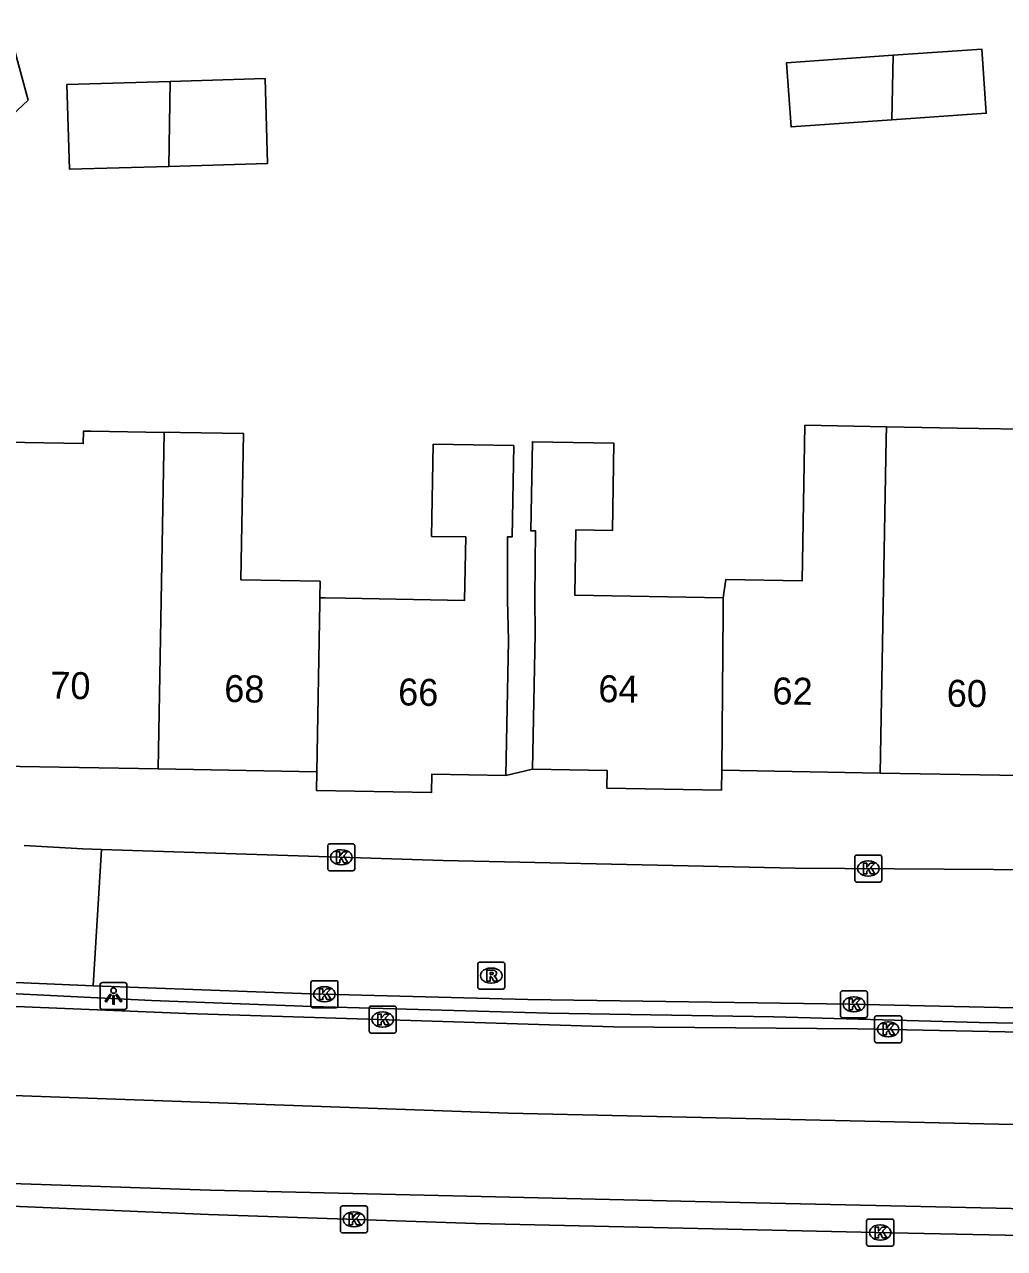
# Model space of a CAD drawing. Extents: x 161845 to 162341, y 381620 to 382158.
# Drawn here: x 162083.32 to 162119.6, y 381620.6 to 381665.94 of the extents above; entities that cross this region are included whole.
import ezdxf

# ---------------------------------------------------------------- set-up
doc = ezdxf.new("R2010")
doc.units = 0
for name, color, linetype in [('IMGEO_Hek', 7, 'Continuous'), ('IMGEO_Kolk', 7, 'Continuous'), ('IMGEO_Lichtpunt', 7, 'Continuous'), ('IMGEO_Pand', 7, 'Continuous'), ('IMGEO_Pand_nummerreeks', 7, 'Continuous'), ('IMGEO_Rijbaan_lokaal_open', 7, 'Continuous'), ('IMGEO_Rijbaan_regionaal_gesloten', 7, 'Continuous'), ('IMGEO_Rioolput', 7, 'Continuous'), ('IMGEO_Voetpad_open', 7, 'Continuous')]:
    doc.layers.add(name, color=color, linetype=linetype)

msp = doc.modelspace()

# ---------------------------------------------------------------- linework, layer by layer
at = {"layer": 'IMGEO_Hek'}
msp.add_lwpolyline([(162137.794, 381628.704), (162131.639, 381628.756), (162127.198, 381628.815), (162118.656, 381628.981), (162111.06, 381629.186), (162102.721, 381629.322), (162093.959, 381629.569), (162088.027, 381629.796), (162079.036, 381630.235), (162074.46, 381630.502), (162066.472, 381631.038), (162058.311, 381631.695), (162053.276, 381632.163), (162034.557, 381634.329), (162000, 381638.941), (161983.372, 381641.239)], dxfattribs=at)
at = {"layer": 'IMGEO_Kolk'}
for p, q in [((162094.547, 381634.669), (162094.547, 381635.521)), ((162094.622, 381635.595), (162095.474, 381635.595)), ((162095.035, 381635.375), (162095.06, 381635.375)), ((162095.548, 381635.521), (162095.548, 381634.669)), ((162114.132, 381635.179), (162114.984, 381635.179)), ((162095.058, 381634.815), (162095.033, 381634.815)), ((162114.057, 381634.253), (162114.057, 381635.105)), ((162114.545, 381634.959), (162114.57, 381634.959)), ((162115.058, 381635.105), (162115.058, 381634.253)), ((162095.474, 381634.595), (162094.622, 381634.595)), ((162114.568, 381634.399), (162114.543, 381634.399)), ((162114.984, 381634.179), (162114.132, 381634.179)), ((162093.926, 381629.597), (162093.926, 381630.449)), ((162094.001, 381630.523), (162094.853, 381630.523)), ((162094.414, 381630.303), (162094.439, 381630.303)), ((162094.927, 381630.449), (162094.927, 381629.597)), ((162094.437, 381629.743), (162094.412, 381629.743)), ((162113.526, 381629.224), (162113.526, 381630.076)), ((162113.601, 381630.15), (162114.453, 381630.15)), ((162114.014, 381629.93), (162114.039, 381629.93)), ((162114.527, 381630.076), (162114.527, 381629.224)), ((162094.853, 381629.523), (162094.001, 381629.523)), ((162096.082, 381628.66), (162096.082, 381629.512)), ((162096.157, 381629.586), (162097.009, 381629.586)), ((162096.57, 381629.366), (162096.595, 381629.366)), ((162097.083, 381629.512), (162097.083, 381628.66)), ((162114.037, 381629.37), (162114.012, 381629.37)), ((162096.593, 381628.806), (162096.568, 381628.806)), ((162114.453, 381629.15), (162113.601, 381629.15)), ((162114.792, 381628.297), (162114.792, 381629.149)), ((162114.867, 381629.223), (162115.719, 381629.223)), ((162115.28, 381629.003), (162115.305, 381629.003)), ((162115.793, 381629.149), (162115.793, 381628.297)), ((162097.009, 381628.586), (162096.157, 381628.586)), ((162115.303, 381628.443), (162115.278, 381628.443)), ((162115.719, 381628.223), (162114.867, 381628.223)), ((162095.018, 381621.259), (162095.018, 381622.111)), ((162095.093, 381622.185), (162095.945, 381622.185)), ((162096.019, 381622.111), (162096.019, 381621.259)), ((162095.506, 381621.965), (162095.531, 381621.965)), ((162114.496, 381620.771), (162114.496, 381621.623)), ((162114.571, 381621.697), (162115.423, 381621.697)), ((162115.497, 381621.623), (162115.497, 381620.771)), ((162095.945, 381621.185), (162095.093, 381621.185)), ((162095.529, 381621.405), (162095.504, 381621.405)), ((162114.984, 381621.477), (162115.009, 381621.477)), ((162115.423, 381620.697), (162114.571, 381620.697)), ((162115.007, 381620.917), (162114.982, 381620.917))]:
    msp.add_line(p, q, dxfattribs=at)
for points in [[(162094.547, 381634.669), (162094.547, 381635.521)], [(162094.622, 381635.595), (162095.474, 381635.595)], [(162094.868, 381635.295), (162094.991, 381635.295), (162094.991, 381635.144), (162095.121, 381635.295), (162095.285, 381635.295), (162095.139, 381635.144), (162095.292, 381634.895), (162095.14, 381634.895), (162095.055, 381635.059), (162094.991, 381634.992), (162094.991, 381634.895), (162094.868, 381634.895), (162094.868, 381635.295)], [(162095.548, 381635.521), (162095.548, 381634.669)], [(162114.132, 381635.179), (162114.984, 381635.179)], [(162114.057, 381634.253), (162114.057, 381635.105)], [(162114.378, 381634.879), (162114.501, 381634.879), (162114.501, 381634.728), (162114.631, 381634.879), (162114.795, 381634.879), (162114.649, 381634.728), (162114.802, 381634.479), (162114.65, 381634.479), (162114.565, 381634.643), (162114.501, 381634.576), (162114.501, 381634.479), (162114.378, 381634.479), (162114.378, 381634.879)], [(162115.058, 381635.105), (162115.058, 381634.253)], [(162095.474, 381634.595), (162094.622, 381634.595)], [(162114.984, 381634.179), (162114.132, 381634.179)], [(162093.926, 381629.597), (162093.926, 381630.449)], [(162094.001, 381630.523), (162094.853, 381630.523)], [(162094.247, 381630.223), (162094.37, 381630.223), (162094.37, 381630.072), (162094.5, 381630.223), (162094.664, 381630.223), (162094.518, 381630.072), (162094.671, 381629.823), (162094.519, 381629.823), (162094.434, 381629.987), (162094.37, 381629.92), (162094.37, 381629.823), (162094.247, 381629.823), (162094.247, 381630.223)], [(162094.927, 381630.449), (162094.927, 381629.597)], [(162113.526, 381629.224), (162113.526, 381630.076)], [(162113.601, 381630.15), (162114.453, 381630.15)], [(162113.847, 381629.85), (162113.97, 381629.85), (162113.97, 381629.699), (162114.1, 381629.85), (162114.264, 381629.85), (162114.118, 381629.699), (162114.271, 381629.45), (162114.119, 381629.45), (162114.034, 381629.614), (162113.97, 381629.547), (162113.97, 381629.45), (162113.847, 381629.45), (162113.847, 381629.85)], [(162114.527, 381630.076), (162114.527, 381629.224)], [(162094.853, 381629.523), (162094.001, 381629.523)], [(162096.082, 381628.66), (162096.082, 381629.512)], [(162096.157, 381629.586), (162097.009, 381629.586)], [(162096.403, 381629.286), (162096.526, 381629.286), (162096.526, 381629.135), (162096.656, 381629.286), (162096.82, 381629.286), (162096.674, 381629.135), (162096.827, 381628.886), (162096.675, 381628.886), (162096.59, 381629.05), (162096.526, 381628.983), (162096.526, 381628.886), (162096.403, 381628.886), (162096.403, 381629.286)], [(162097.083, 381629.512), (162097.083, 381628.66)], [(162114.453, 381629.15), (162113.601, 381629.15)], [(162114.792, 381628.297), (162114.792, 381629.149)], [(162114.867, 381629.223), (162115.719, 381629.223)], [(162115.113, 381628.923), (162115.236, 381628.923), (162115.236, 381628.772), (162115.366, 381628.923), (162115.53, 381628.923), (162115.384, 381628.772), (162115.537, 381628.523), (162115.385, 381628.523), (162115.3, 381628.687), (162115.236, 381628.62), (162115.236, 381628.523), (162115.113, 381628.523), (162115.113, 381628.923)], [(162115.793, 381629.149), (162115.793, 381628.297)], [(162097.009, 381628.586), (162096.157, 381628.586)], [(162115.719, 381628.223), (162114.867, 381628.223)], [(162095.018, 381621.259), (162095.018, 381622.111)], [(162095.093, 381622.185), (162095.945, 381622.185)], [(162096.019, 381622.111), (162096.019, 381621.259)], [(162095.339, 381621.885), (162095.462, 381621.885), (162095.462, 381621.734), (162095.592, 381621.885), (162095.756, 381621.885), (162095.61, 381621.734), (162095.763, 381621.485), (162095.611, 381621.485), (162095.526, 381621.649), (162095.462, 381621.582), (162095.462, 381621.485), (162095.339, 381621.485), (162095.339, 381621.885)], [(162114.496, 381620.771), (162114.496, 381621.623)], [(162114.571, 381621.697), (162115.423, 381621.697)], [(162115.497, 381621.623), (162115.497, 381620.771)], [(162095.945, 381621.185), (162095.093, 381621.185)], [(162114.817, 381621.397), (162114.94, 381621.397), (162114.94, 381621.246), (162115.07, 381621.397), (162115.234, 381621.397), (162115.088, 381621.246), (162115.241, 381620.997), (162115.089, 381620.997), (162115.004, 381621.161), (162114.94, 381621.094), (162114.94, 381620.997), (162114.817, 381620.997), (162114.817, 381621.397)], [(162115.423, 381620.697), (162114.571, 381620.697)]]:
    msp.add_lwpolyline(points, dxfattribs=at)
for centre, start, end in [((162094.624, 381635.519), 91.552, 178.448), ((162094.624, 381635.519), 91.552, 178.448), ((162095.472, 381635.519), 1.552, 88.448), ((162095.472, 381635.519), 1.552, 88.448), ((162114.134, 381635.103), 91.552, 178.448), ((162114.134, 381635.103), 91.552, 178.448), ((162114.982, 381635.103), 1.552, 88.448), ((162114.982, 381635.103), 1.552, 88.448), ((162094.624, 381634.671), 181.552, 268.448), ((162094.624, 381634.671), 181.552, 268.448), ((162095.472, 381634.671), 271.552, 358.448), ((162095.472, 381634.671), 271.552, 358.448), ((162114.134, 381634.255), 181.552, 268.448), ((162114.134, 381634.255), 181.552, 268.448), ((162114.982, 381634.255), 271.552, 358.448), ((162114.982, 381634.255), 271.552, 358.448), ((162094.003, 381630.447), 91.552, 178.448), ((162094.003, 381630.447), 91.552, 178.448), ((162094.851, 381630.447), 1.552, 88.448), ((162094.851, 381630.447), 1.552, 88.448), ((162113.603, 381630.074), 91.552, 178.448), ((162113.603, 381630.074), 91.552, 178.448), ((162114.451, 381630.074), 1.552, 88.448), ((162114.451, 381630.074), 1.552, 88.448), ((162094.003, 381629.599), 181.552, 268.448), ((162094.003, 381629.599), 181.552, 268.448), ((162094.851, 381629.599), 271.552, 358.448), ((162094.851, 381629.599), 271.552, 358.448), ((162096.159, 381629.51), 91.552, 178.448), ((162096.159, 381629.51), 91.552, 178.448), ((162097.007, 381629.51), 1.552, 88.448), ((162097.007, 381629.51), 1.552, 88.448), ((162113.603, 381629.226), 181.552, 268.448), ((162113.603, 381629.226), 181.552, 268.448), ((162114.451, 381629.226), 271.552, 358.448), ((162114.451, 381629.226), 271.552, 358.448), ((162114.869, 381629.147), 91.552, 178.448), ((162114.869, 381629.147), 91.552, 178.448), ((162115.717, 381629.147), 1.552, 88.448), ((162115.717, 381629.147), 1.552, 88.448), ((162096.159, 381628.662), 181.552, 268.448), ((162096.159, 381628.662), 181.552, 268.448), ((162097.007, 381628.662), 271.552, 358.448), ((162097.007, 381628.662), 271.552, 358.448), ((162114.869, 381628.299), 181.552, 268.448), ((162114.869, 381628.299), 181.552, 268.448), ((162115.717, 381628.299), 271.552, 358.448), ((162115.717, 381628.299), 271.552, 358.448), ((162095.095, 381622.109), 91.552, 178.448), ((162095.095, 381622.109), 91.552, 178.448), ((162095.943, 381622.109), 1.552, 88.448), ((162095.943, 381622.109), 1.552, 88.448), ((162114.573, 381621.621), 91.552, 178.448), ((162114.573, 381621.621), 91.552, 178.448), ((162115.421, 381621.621), 1.552, 88.448), ((162115.421, 381621.621), 1.552, 88.448), ((162095.095, 381621.261), 181.552, 268.448), ((162095.095, 381621.261), 181.552, 268.448), ((162095.943, 381621.261), 271.552, 358.448), ((162095.943, 381621.261), 271.552, 358.448), ((162114.573, 381620.773), 181.552, 268.448), ((162114.573, 381620.773), 181.552, 268.448), ((162115.421, 381620.773), 271.552, 358.448), ((162115.421, 381620.773), 271.552, 358.448)]:
    msp.add_arc(centre, 0.0765, start, end, dxfattribs=at)
for centre, major_axis, ratio, start_param, end_param in [((162095.034, 381635.095), (-0.387, 0.002), 0.722429, 4.712389, 7.853982), ((162095.059, 381635.095), (-0.39, 0.002), 0.717154, 1.570796, 4.712389), ((162114.544, 381634.679), (-0.387, 0.002), 0.722429, 4.712389, 7.853982), ((162114.569, 381634.679), (-0.39, 0.002), 0.717154, 1.570796, 4.712389), ((162094.413, 381630.023), (-0.387, 0.002), 0.722429, 4.712389, 7.853982), ((162094.438, 381630.023), (-0.39, 0.002), 0.717154, 1.570796, 4.712389), ((162114.013, 381629.65), (-0.387, 0.002), 0.722429, 4.712389, 7.853982), ((162114.038, 381629.65), (-0.39, 0.002), 0.717154, 1.570796, 4.712389), ((162096.569, 381629.086), (-0.387, 0.002), 0.722429, 4.712389, 7.853982), ((162096.594, 381629.086), (-0.39, 0.002), 0.717154, 1.570796, 4.712389), ((162115.279, 381628.723), (-0.387, 0.002), 0.722429, 4.712389, 7.853982), ((162115.304, 381628.723), (-0.39, 0.002), 0.717154, 1.570796, 4.712389), ((162095.505, 381621.685), (-0.387, 0.002), 0.722429, 4.712389, 7.853982), ((162095.53, 381621.685), (-0.39, 0.002), 0.717154, 1.570796, 4.712389), ((162114.983, 381621.197), (-0.387, 0.002), 0.722429, 4.712389, 7.853982), ((162115.008, 381621.197), (-0.39, 0.002), 0.717154, 1.570796, 4.712389)]:
    msp.add_ellipse(centre, major_axis=major_axis, ratio=ratio, start_param=start_param, end_param=end_param, dxfattribs=at)
at = {"layer": 'IMGEO_Lichtpunt'}
for p, q in [((162086.12, 381630.36), (162086.12, 381629.553)), ((162086.12, 381630.36), (162086.12, 381629.553)), ((162087.022, 381630.455), (162086.214, 381630.455)), ((162087.022, 381630.455), (162086.214, 381630.455)), ((162087.116, 381629.553), (162087.116, 381630.36)), ((162087.116, 381629.553), (162087.116, 381630.36)), ((162086.214, 381629.459), (162087.022, 381629.459)), ((162086.214, 381629.459), (162087.022, 381629.459))]:
    msp.add_line(p, q, dxfattribs=at)
for points in [[(162086.494, 381630.024), (162086.533, 381629.996), (162086.345, 381629.734), (162086.307, 381629.761), (162086.494, 381630.024)], [(162086.596, 381629.976), (162086.643, 381629.976), (162086.643, 381629.654), (162086.596, 381629.654), (162086.596, 381629.976)], [(162086.706, 381629.996), (162086.744, 381630.023), (162086.931, 381629.761), (162086.892, 381629.733), (162086.706, 381629.996)]]:
    msp.add_lwpolyline(points, dxfattribs=at)
msp.add_circle((162086.619, 381630.158), 0.0994, dxfattribs=at)
for centre, start, end in [((162086.214, 381630.36), 90, 180), ((162086.214, 381630.36), 90, 180), ((162087.022, 381630.36), 0, 90), ((162087.022, 381630.36), 0, 90), ((162086.214, 381629.553), 180, 270), ((162086.214, 381629.553), 180, 270), ((162087.022, 381629.553), 270, 0), ((162087.022, 381629.553), 270, 360)]:
    msp.add_arc(centre, 0.0946, start, end, dxfattribs=at)
at = {"layer": 'IMGEO_Pand'}
for points in [[(162115.435, 381662.41), (162111.7, 381662.148), (162111.534, 381664.523), (162115.479, 381664.799)], [(162115.479, 381664.799), (162118.76, 381665.03), (162118.926, 381662.654), (162115.435, 381662.41)], [(162115.479, 381664.799), (162115.435, 381662.41)], [(162088.665, 381660.686), (162084.989, 381660.577), (162084.895, 381663.721), (162088.721, 381663.834)], [(162088.721, 381663.834), (162092.226, 381663.938), (162092.32, 381660.794), (162088.665, 381660.686)], [(162088.665, 381660.686), (162088.721, 381663.834)], [(162109.19, 381644.705), (162109.286, 381645.385), (162112.109, 381645.334), (162112.213, 381651.097), (162115.227, 381651.042)], [(162114.993, 381638.213), (162115.219, 381650.579), (162115.227, 381651.042)], [(162115.227, 381651.042), (162117.85, 381650.994), (162121.065, 381650.938), (162120.962, 381645.235), (162120.955, 381644.437)], [(162082.624, 381650.468), (162085.498, 381650.416), (162085.506, 381650.877), (162085.789, 381650.872), (162088.488, 381650.824)], [(162088.265, 381638.369), (162088.488, 381650.824)], [(162088.488, 381650.824), (162088.648, 381650.84), (162089.079, 381650.832), (162091.433, 381650.789), (162091.335, 381645.375), (162094.267, 381645.322), (162094.256, 381644.708)], [(162094.256, 381644.708), (162094.452, 381644.704), (162095.197, 381644.691), (162099.613, 381644.611), (162099.655, 381646.958), (162098.392, 381646.981), (162098.454, 381650.394), (162101.432, 381650.341), (162101.371, 381646.96), (162101.199, 381646.964), (162101.196, 381644.616), (162101.234, 381643.127), (162101.144, 381638.127)], [(162102.129, 381638.355), (162102.22, 381643.355), (162102.215, 381644.723), (162102.244, 381647.186), (162102.065, 381647.189), (162102.125, 381650.488), (162105.142, 381650.433), (162105.083, 381647.193), (162103.733, 381647.218), (162103.689, 381644.805), (162109.19, 381644.705)], [(162094.14, 381638.263), (162094.253, 381644.534), (162094.256, 381644.708)], [(162109.138, 381638.319), (162109.186, 381644.158), (162109.19, 381644.705)], [(162088.265, 381638.369), (162082.409, 381638.475)], [(162094.14, 381638.263), (162088.265, 381638.369)], [(162109.138, 381638.319), (162109.125, 381637.583), (162104.885, 381637.659), (162104.896, 381638.305), (162102.129, 381638.355)], [(162101.144, 381638.127), (162098.402, 381638.177), (162098.389, 381637.492), (162094.128, 381637.569), (162094.14, 381638.263)], [(162114.993, 381638.213), (162109.138, 381638.319)], [(162120.903, 381638.106), (162114.993, 381638.213)]]:
    msp.add_lwpolyline(points, dxfattribs=at)
at = {"layer": 'IMGEO_Rijbaan_lokaal_open'}
for points in [[(162083.314, 381635.535), (162085.478, 381635.405), (162086.17, 381635.382)], [(162086.17, 381635.382), (162085.866, 381630.33)], [(162086.17, 381635.382), (162098.826, 381634.971), (162111.846, 381634.697), (162124.705, 381634.603), (162127.788, 381634.538), (162137.564, 381634.33), (162137.678, 381634.326)], [(162085.866, 381630.33), (162083.008, 381630.46)], [(162147.939, 381629.029), (162139.356, 381629.189), (162137.799, 381629.209), (162128.275, 381629.331), (162113.858, 381629.656), (162101.958, 381629.829), (162093.915, 381630.038), (162085.866, 381630.33)]]:
    msp.add_lwpolyline(points, dxfattribs=at)
at = {"layer": 'IMGEO_Rijbaan_regionaal_gesloten'}
for points in [[(162065.762, 381627.224), (162074.598, 381626.568), (162101.225, 381625.613), (162133.688, 381624.885), (162151.965, 381624.703), (162167.196, 381625.249), (162193.384, 381627.978), (162217.254, 381632.709), (162234.44, 381637.075), (162251.353, 381642.169), (162267.176, 381648.082), (162286.544, 381657.725), (162299.911, 381665.73), (162311.76, 381673.667)], [(162149.027, 381628.158), (162137.79, 381628.303), (162136.248, 381628.323), (162126.306, 381628.493), (162114.157, 381628.746), (162105.124, 381628.816), (162089.317, 381629.313), (162079.706, 381629.703), (162074.823, 381630.031), (162066.237, 381630.607)], [(162166.914, 381621.301), (162156.441, 381620.733), (162153.994, 381620.605), (162134.53, 381620.776), (162126.197, 381620.966), (162114.837, 381621.198), (162100.02, 381621.534), (162090.138, 381621.864), (162075.85, 381622.469), (162074.337, 381622.567), (162068.187, 381622.967), (162063.349, 381623.412)], [(162081.716, 381623.053), (162090.199, 381622.764), (162108.154, 381622.345), (162120.952, 381622.061), (162134.521, 381621.806), (162145.632, 381621.574)]]:
    msp.add_lwpolyline(points, dxfattribs=at)
at = {"layer": 'IMGEO_Rioolput'}
for p, q in [((162100.101, 381630.287), (162100.101, 381631.139)), ((162100.176, 381631.213), (162101.028, 381631.213)), ((162101.102, 381631.139), (162101.102, 381630.287)), ((162100.589, 381630.993), (162100.614, 381630.993)), ((162101.028, 381630.213), (162100.176, 381630.213)), ((162100.612, 381630.433), (162100.587, 381630.433))]:
    msp.add_line(p, q, dxfattribs=at)
for points in [[(162100.101, 381630.287), (162100.101, 381631.139)], [(162100.176, 381631.213), (162101.028, 381631.213)], [(162101.102, 381631.139), (162101.102, 381630.287)], [(162100.69, 381630.911), (162100.438, 381630.913), (162100.438, 381630.513)], [(162100.438, 381630.513), (162100.562, 381630.513), (162100.562, 381630.675), (162100.573, 381630.675)], [(162100.616, 381630.832), (162100.562, 381630.832), (162100.562, 381630.751)], [(162100.562, 381630.751), (162100.614, 381630.751)], [(162100.62, 381630.646), (162100.691, 381630.513), (162100.831, 381630.513), (162100.766, 381630.639)], [(162101.028, 381630.213), (162100.176, 381630.213)]]:
    msp.add_lwpolyline(points, dxfattribs=at)
for centre, radius, start, end in [((162100.178, 381631.137), 0.0765, 91.552, 178.448), ((162100.178, 381631.137), 0.0765, 91.552, 178.448), ((162101.026, 381631.137), 0.0765, 1.552, 88.448), ((162101.026, 381631.137), 0.0765, 1.552, 88.448), ((162100.572, 381630.622), 0.0533, 26.0293, 88.6989), ((162100.598, 381630.94), 0.19, 274.7715, 282.9687), ((162100.622, 381630.736), 0.0964, 77.0061, 93.1865), ((162100.636, 381630.793), 0.0378, 276.6634, 79.6772), ((162100.689, 381630.801), 0.109, 350.3612, 89.416), ((162100.687, 381630.801), 0.112, 277.5842, 350.9817), ((162100.671, 381630.586), 0.108, 29.5134, 73.7905), ((162100.178, 381630.289), 0.0765, 181.552, 268.448), ((162100.178, 381630.289), 0.0765, 181.552, 268.448), ((162101.026, 381630.289), 0.0765, 271.552, 358.448), ((162101.026, 381630.289), 0.0765, 271.552, 358.448)]:
    msp.add_arc(centre, radius, start, end, dxfattribs=at)
for centre, major_axis, ratio, start_param, end_param in [((162100.588, 381630.713), (-0.387, 0.002), 0.722429, 4.712389, 7.853982), ((162100.613, 381630.713), (-0.39, 0.002), 0.717154, 1.570796, 4.712389)]:
    msp.add_ellipse(centre, major_axis=major_axis, ratio=ratio, start_param=start_param, end_param=end_param, dxfattribs=at)
at = {"layer": 'IMGEO_Voetpad_open'}
for points in [[(162068.379, 381661.411), (162072.739, 381661.332), (162076.93, 381661.252), (162078.735, 381661.272), (162079.661, 381662.314), (162081.862, 381661.656), (162083.454, 381663.134), (162082.012, 381668.432), (162093.269, 381698.426)], [(162101.144, 381638.127), (162102.129, 381638.355)]]:
    msp.add_lwpolyline(points, dxfattribs=at)

# ---------------------------------------------------------------- texts
at = {"layer": 'IMGEO_Pand_nummerreeks'}
for s, rotation, p in [('70', 358.8885, (162084.269, 381640.974)), ('68', 358.8885, (162090.709, 381640.85)), ('66', 358.8885, (162097.146, 381640.725)), ('64', 359.2469, (162104.56, 381640.843)), ('62', 359.2469, (162111.004, 381640.759)), ('60', 359.2494, (162117.457, 381640.674))]:
    msp.add_text(s, height=1, rotation=rotation, dxfattribs=at).set_placement(p)

doc.saveas('drawing.dxf')
